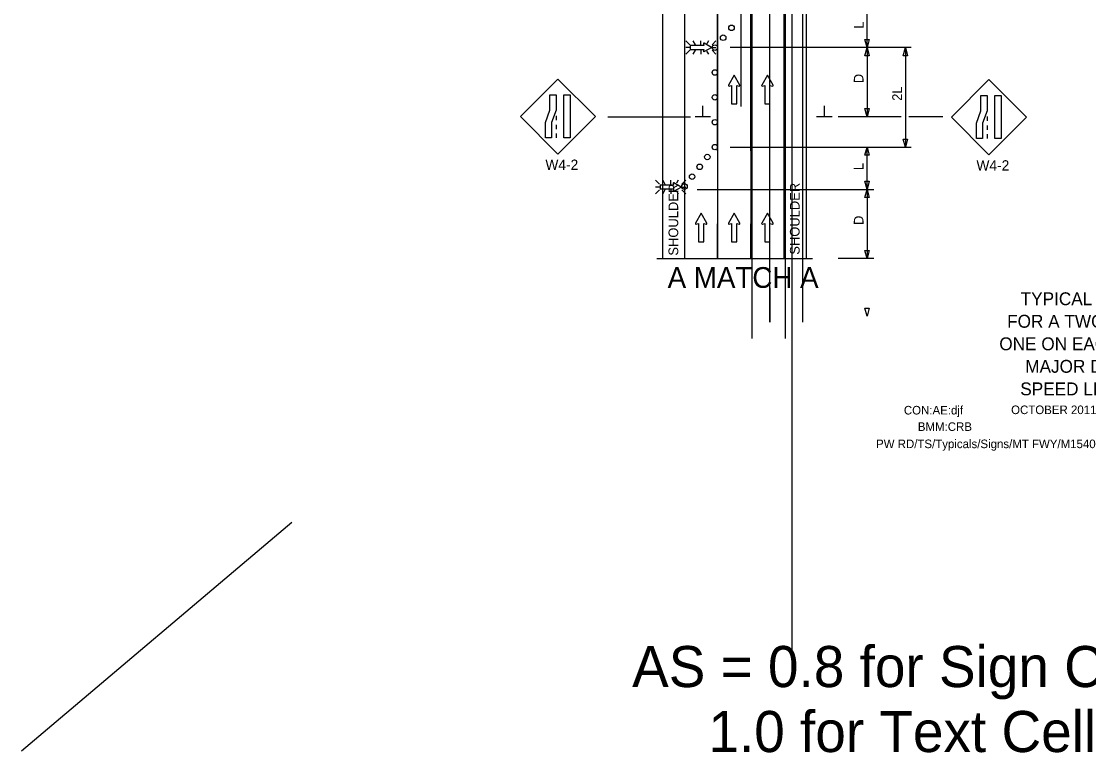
# Model space of a CAD drawing. Extents: x 16452 to 19504, y 5713 to 7079.
# Drawn here: x 16452 to 17224, y 5713 to 6242 of the extents above; entities that cross this region are included whole.
import ezdxf

# ---------------------------------------------------------------- set-up
doc = ezdxf.new("R2010")
doc.units = 0
for name, color, linetype in [('ALI_LEGAL_EX', 7, 'Continuous'), ('BORDER', 7, 'Continuous'), ('BORDER_SIGNAL_WO', 7, 'Continuous'), ('MT_SCRATCH_LEVEL_E', 7, 'Continuous'), ('PAVT_EDGE_EX', 7, 'Continuous'), ('TRAFFIC_SIGNS_PR', 7, 'Continuous'), ('TYPICAL_TEXT_DIMEN_PR', 7, 'Continuous')]:
    doc.layers.add(name, color=color, linetype=linetype)

msp = doc.modelspace()

# ---------------------------------------------------------------- linework, layer by layer
at = {"layer": 'ALI_LEGAL_EX'}
for p, q in [((16980.68, 7015.93), (16980.68, 6197.8)), ((17004.68, 7015.93), (17004.68, 6197.8)), ((16980.68, 6877.04), (16980.68, 6013.12)), ((17004.68, 6877.04), (17004.68, 6013.12)), ((16973.01, 6180.85), (16973.01, 6681.19)), ((16993.65, 6024.8), (16993.65, 6525.15)), ((17017.65, 6024.8), (17017.65, 6525.15)), ((16955.93, 6148.9), (16955.93, 6425.58)), ((16979.93, 6148.9), (16979.93, 6425.58)), ((17009.75, 5773.57), (17009.75, 6383.76))]:
    msp.add_line(p, q, dxfattribs=at)
for points in [[(16955.93, 6170.95), (16955.93, 6195.95)], [(16979.93, 6170.95), (16979.93, 6195.95)], [(16955.93, 6070.95), (16955.93, 6095.95)], [(16979.93, 6070.95), (16979.93, 6095.95)], [(16993.65, 6049.8), (16993.65, 6024.8)]]:
    msp.add_lwpolyline(points, dxfattribs=at)
at = {"layer": 'MT_SCRATCH_LEVEL_E'}
for p, q in [((16967.85, 6203.62), (16963.74, 6196.38)), ((16972, 6196.38), (16967.85, 6203.62)), ((16991.9, 6203.62), (16987.79, 6196.38)), ((16996.05, 6196.38), (16991.9, 6203.62)), ((16964.22, 6195.7), (16966, 6196.01)), ((16966, 6196.01), (16966, 6182.75)), ((16969.74, 6182.75), (16969.74, 6196.01)), ((16969.74, 6196.01), (16971.52, 6195.7)), ((16988.27, 6195.7), (16990.05, 6196.01)), ((16990.05, 6196.01), (16990.05, 6182.75)), ((16993.79, 6182.75), (16993.79, 6196.01)), ((16993.79, 6196.01), (16995.57, 6195.7)), ((16966, 6182.75), (16969.74, 6182.75)), ((16990.05, 6182.75), (16993.79, 6182.75)), ((16943.95, 6103.76), (16939.84, 6096.52)), ((16948.09, 6096.52), (16943.95, 6103.76)), ((16967.85, 6103.76), (16963.74, 6096.52)), ((16972, 6096.52), (16967.85, 6103.76)), ((16991.9, 6103.76), (16987.79, 6096.52)), ((16996.05, 6096.52), (16991.9, 6103.76)), ((16940.32, 6095.83), (16942.1, 6096.15)), ((16942.1, 6096.15), (16942.1, 6082.89)), ((16945.84, 6082.89), (16945.84, 6096.15)), ((16945.84, 6096.15), (16947.61, 6095.83)), ((16964.22, 6095.83), (16966, 6096.15)), ((16966, 6096.15), (16966, 6082.89)), ((16969.74, 6082.89), (16969.74, 6096.15)), ((16969.74, 6096.15), (16971.52, 6095.83)), ((16988.27, 6095.83), (16990.05, 6096.15)), ((16990.05, 6096.15), (16990.05, 6082.89)), ((16993.79, 6082.89), (16993.79, 6096.15)), ((16993.79, 6096.15), (16995.57, 6095.83)), ((16942.1, 6082.89), (16945.84, 6082.89)), ((16966, 6082.89), (16969.74, 6082.89)), ((16990.05, 6082.89), (16993.79, 6082.89))]:
    msp.add_line(p, q, dxfattribs=at)
for centre, start, end in [((16964.15, 6196.16), 150.42484, 279.96381), ((16971.59, 6196.16), 260.03619, 29.77312), ((16988.2, 6196.16), 150.42484, 279.96381), ((16995.64, 6196.16), 260.03619, 29.77312), ((16940.24, 6096.29), 150.42484, 279.96381), ((16947.68, 6096.29), 260.03619, 29.77312), ((16964.15, 6096.29), 150.42484, 279.96381), ((16971.59, 6096.29), 260.03619, 29.77312), ((16988.2, 6096.29), 150.42484, 279.96381), ((16995.64, 6096.29), 260.03619, 29.77312)]:
    msp.add_arc(centre, 0.463, start, end, dxfattribs=at)
at = {"layer": 'PAVT_EDGE_EX'}
for p, q in [((16915.93, 6425.58), (16915.93, 6070.95)), ((16931.93, 6425.58), (16931.93, 6070.95)), ((16955.93, 6425.58), (16955.93, 6070.95)), ((16979.93, 6425.58), (16979.93, 6070.95)), ((17003.93, 6425.58), (17003.93, 6070.95)), ((17019.93, 6425.58), (17019.93, 6070.95))]:
    msp.add_line(p, q, dxfattribs=at)
at = {"layer": 'TRAFFIC_SIGNS_PR'}
for p, q in [((16935.71, 6225.61), (16932.89, 6228.44)), ((16938, 6228.43), (16939.63, 6225.61)), ((16943.79, 6225.61), (16943.79, 6228.43)), ((16949.26, 6228.43), (16948.05, 6226.34)), ((16954.69, 6228.43), (16951.88, 6225.61)), ((16935.71, 6223.58), (16932.89, 6223.58)), ((16935.71, 6221.55), (16932.89, 6218.73)), ((16939.66, 6221.55), (16938.03, 6218.73)), ((16943.79, 6221.55), (16943.79, 6218.73)), ((16947.97, 6220.92), (16949.24, 6218.73)), ((16951.88, 6223.58), (16954.69, 6223.58)), ((16954.69, 6218.73), (16951.88, 6221.55)), ((16840.31, 6200.78), (16813.16, 6173.63)), ((16867.46, 6173.63), (16840.31, 6200.78)), ((17152.24, 6200.3), (17125.08, 6173.15)), ((17179.39, 6173.15), (17152.24, 6200.3)), ((16813.16, 6173.63), (16840.31, 6146.48)), ((16839.06, 6174.12), (16839.06, 6170.92)), ((16840.31, 6146.48), (16867.46, 6173.63)), ((17125.08, 6173.15), (17152.24, 6145.99)), ((17150.99, 6173.64), (17150.99, 6170.44)), ((17152.24, 6145.99), (17179.39, 6173.15)), ((16839.06, 6167.72), (16839.06, 6164.52)), ((17150.99, 6167.24), (17150.99, 6164.04)), ((16839.06, 6161.32), (16839.06, 6158.12)), ((17150.99, 6160.84), (17150.99, 6157.64)), ((16913.83, 6124.66), (16911.01, 6127.48)), ((16916.13, 6127.48), (16917.76, 6124.66)), ((16921.92, 6124.66), (16921.92, 6127.48)), ((16927.39, 6127.48), (16926.18, 6125.39)), ((16932.82, 6127.48), (16930, 6124.66)), ((16913.83, 6122.63), (16911.01, 6122.63)), ((16913.83, 6120.6), (16911.01, 6117.78)), ((16917.78, 6120.6), (16916.15, 6117.78)), ((16921.92, 6120.6), (16921.92, 6117.78)), ((16926.1, 6119.96), (16927.36, 6117.78)), ((16930, 6122.63), (16932.82, 6122.63)), ((16932.82, 6117.78), (16930, 6120.6))]:
    msp.add_line(p, q, dxfattribs=at)
for points in [[(16945.62, 6226.26), (16945.85, 6224.97), (16936.12, 6224.97), (16936.12, 6222.22), (16945.85, 6222.22), (16945.62, 6220.92)], [(16946.12, 6220.57), (16951.43, 6223.58), (16946.12, 6226.62)], [(16923.74, 6125.31), (16923.97, 6124.02), (16914.25, 6124.02), (16914.25, 6121.27), (16923.97, 6121.27), (16923.74, 6119.97)], [(16924.24, 6119.62), (16929.55, 6122.63), (16924.24, 6125.67)]]:
    msp.add_lwpolyline(points, dxfattribs=at)
for points in [[(16839.06, 6189.37), (16839.06, 6178.19), (16835.72, 6169.3), (16835.72, 6158.12), (16831.22, 6158.12), (16831.22, 6169.3), (16834.57, 6178.19), (16834.57, 6189.37)], [(16849.2, 6189.37), (16849.2, 6158.12), (16844.7, 6158.12), (16844.7, 6189.37)], [(17150.99, 6188.88), (17150.99, 6177.7), (17147.65, 6168.82), (17147.65, 6157.64), (17143.15, 6157.64), (17143.15, 6168.82), (17146.5, 6177.7), (17146.5, 6188.88)], [(17161.13, 6188.88), (17161.13, 6157.64), (17156.63, 6157.64), (17156.63, 6188.88)]]:
    msp.add_lwpolyline(points, close=True, dxfattribs=at)
for centre in [(16965.93, 6237.79), (16953.93, 6223.51), (16959.93, 6230.65), (16953.93, 6205.51), (16953.93, 6187.51), (16953.93, 6169.51), (16953.93, 6151.51), (16948.43, 6144.38), (16942.94, 6137.25), (16937.44, 6130.12), (16931.94, 6123)]:
    msp.add_circle(centre, 2, dxfattribs=at)
for centre, start, end in [((16945.95, 6226.32), 61.48329, 189.95933), ((16945.95, 6220.87), 170.73078, 298.89165), ((16924.08, 6125.37), 61.48329, 189.95933), ((16924.08, 6119.91), 170.73078, 298.89165)]:
    msp.add_arc(centre, 0.341, start, end, dxfattribs=at)
at = {"layer": 'TYPICAL_TEXT_DIMEN_PR'}
for p, q in [((17064.03, 6223.51), (17064.03, 6252.07)), ((17064.03, 6223.51), (17062.46, 6229.37)), ((17062.46, 6229.37), (17064.03, 6229.37)), ((17064.03, 6229.37), (17065.6, 6229.37)), ((17065.6, 6229.37), (17064.03, 6223.51)), ((17096.07, 6223.51), (16964.93, 6223.51)), ((17062.46, 6217.65), (17064.03, 6223.51)), ((17064.03, 6223.51), (17064.03, 6173.51)), ((17064.03, 6223.51), (17065.6, 6217.65)), ((17090.26, 6217.65), (17091.83, 6223.51)), ((17091.83, 6223.51), (17093.4, 6217.65)), ((17091.83, 6223.51), (17091.83, 6151.51)), ((17064.03, 6217.65), (17062.46, 6217.65)), ((17065.6, 6217.65), (17064.03, 6217.65)), ((17091.83, 6217.65), (17090.26, 6217.65)), ((17093.4, 6217.65), (17091.83, 6217.65)), ((16945.22, 6173.51), (16945.22, 6181.3)), ((17033.15, 6173.51), (17033.15, 6181.3)), ((17064.03, 6173.51), (17062.46, 6179.37)), ((17062.46, 6179.37), (17064.03, 6179.37)), ((17064.03, 6179.37), (17065.6, 6179.37)), ((17065.6, 6179.37), (17064.03, 6173.51)), ((16876.41, 6173.51), (16936.23, 6173.51)), ((16950.84, 6173.51), (16939.59, 6173.51)), ((17038.78, 6173.51), (17027.53, 6173.51)), ((17088.65, 6173.51), (17043.03, 6173.51)), ((17118.85, 6173.51), (17094.37, 6173.51)), ((17091.83, 6151.51), (17090.26, 6157.37)), ((17090.26, 6157.37), (17091.83, 6157.37)), ((17091.83, 6157.37), (17093.4, 6157.37)), ((17093.4, 6157.37), (17091.83, 6151.51)), ((16964.93, 6151.51), (17096.07, 6151.51)), ((17062.46, 6145.65), (17064.03, 6151.51)), ((17064.03, 6120.95), (17064.03, 6151.51)), ((17064.03, 6151.51), (17065.6, 6145.65)), ((17064.03, 6145.65), (17062.46, 6145.65)), ((17065.6, 6145.65), (17064.03, 6145.65)), ((17064.03, 6120.95), (17062.46, 6126.81)), ((17062.46, 6126.81), (17064.03, 6126.81)), ((17064.03, 6126.81), (17065.6, 6126.81)), ((17065.6, 6126.81), (17064.03, 6120.95)), ((16941.19, 6120.95), (17069.03, 6120.95)), ((17062.46, 6115.09), (17064.03, 6120.95)), ((17064.03, 6120.95), (17064.03, 6070.95)), ((17064.03, 6120.95), (17065.6, 6115.09)), ((17064.03, 6115.09), (17062.46, 6115.09)), ((17065.6, 6115.09), (17064.03, 6115.09)), ((17064.03, 6070.95), (17062.46, 6076.81)), ((17062.46, 6076.81), (17064.03, 6076.81)), ((17064.03, 6076.81), (17065.6, 6076.81)), ((17065.6, 6076.81), (17064.03, 6070.95)), ((16912, 6070.95), (17024.65, 6070.95)), ((17069.03, 6070.95), (17043.03, 6070.95)), ((17064.03, 6029.13), (17062.46, 6035)), ((17062.46, 6035), (17064.03, 6035)), ((17064.03, 6035), (17065.6, 6035)), ((17065.6, 6035), (17064.03, 6029.13)), ((16647.75, 5880), (16452.02, 5714.53))]:
    msp.add_line(p, q, dxfattribs=at)

# ---------------------------------------------------------------- texts
at = {"layer": 'BORDER'}
for s, p in [('TYPICAL TEMPORARY TRAFFIC CONTROL', (17175.21, 6037.14)), ('FOR A TWO-LANE CLOSURE ON A FREEWAY,', (17165.41, 6020.84)), ('ONE ON EACH SIDE OF A GORE AREA AT A ', (17159.75, 6004.54)), ('MAJOR DIVERGENCE USING A REDUCED', (17178.52, 5988.24)), ('SPEED LIMIT WHERE WORKERS PRESENT', (17174.92, 5971.94))]:
    msp.add_text(s, height=9.3, dxfattribs=at).set_placement(p)
at = {"layer": 'BORDER_SIGNAL_WO'}
for s, height, p in [('CON:AE:djf  ', 6.2, (17090.69, 5958.06)), ('    OCTOBER 2011    ', 6.2, (17159.08, 5958.34)), ('BMM:CRB   ', 6.2, (17100.81, 5946.17)), ('PW RD/TS/Typicals/Signs/MT FWY/M1540a.dgn      ', 6.2, (17070.55, 5933.71)), ('AS = 0.8 for Sign Cells', 29.7271, (16894.01, 5760.83)), ('     1.0 for Text Cells', 29.7271, (16894.01, 5713.82))]:
    msp.add_text(s, height=height, dxfattribs=at).set_placement(p)
at = {"layer": 'TRAFFIC_SIGNS_PR'}
for p in [(16831.27, 6135.04), (17143.2, 6134.55)]:
    msp.add_text('W4-2', height=7.44, dxfattribs=at).set_placement(p)
at = {"layer": 'TYPICAL_TEXT_DIMEN_PR'}
for s, p in [('L', (17061.56, 6237.15)), ('D', (17061.47, 6197.73)), ('2L', (17089.28, 6185.01)), ('L', (17061.47, 6134.8)), ('SHOULDER', (17015.23, 6073.65)), ('SHOULDER', (16927.37, 6072.98)), ('D', (17061.47, 6095.17))]:
    msp.add_text(s, height=7, rotation=90, dxfattribs=at).set_placement(p)
msp.add_text('A MATCH A', height=15, dxfattribs=at).set_placement((16919.74, 6049.68))

doc.saveas('drawing.dxf')
